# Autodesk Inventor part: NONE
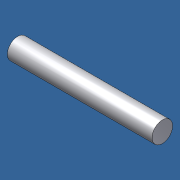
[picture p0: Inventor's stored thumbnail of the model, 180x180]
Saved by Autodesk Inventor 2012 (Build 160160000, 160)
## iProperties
Created: 2013-10
Part Number: NONE
Material: Default
Document SubType Name: Modeling
Designer: Admin
Density: 1 g/cm^3
Author: Admin
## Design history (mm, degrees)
node "Sankq_Base_20x201"
node "Base1"
body "Solid1"
